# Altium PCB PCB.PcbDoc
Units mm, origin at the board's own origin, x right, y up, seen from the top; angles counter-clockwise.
Board outline 41 x 25.36 mm, 2 copper layers (TOP, BOTTOM), stack 1.586 mm thick; 42 components, 24 nets, 110 pads, 43 vias.
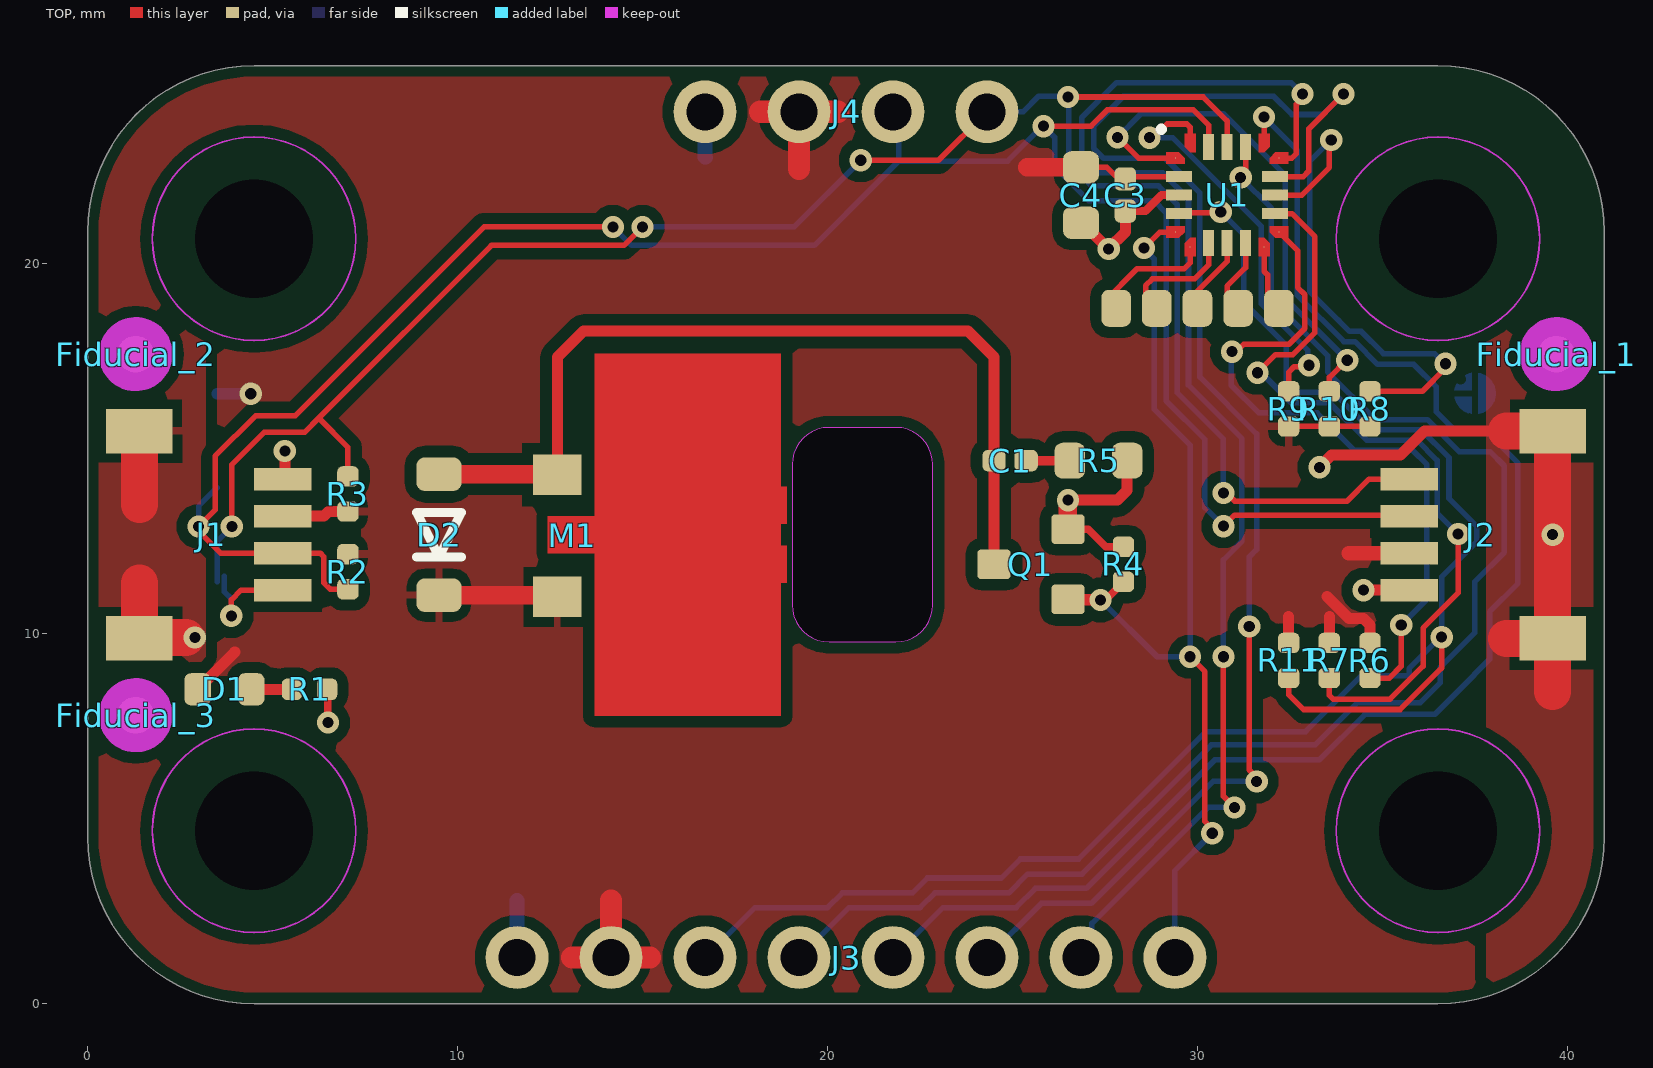
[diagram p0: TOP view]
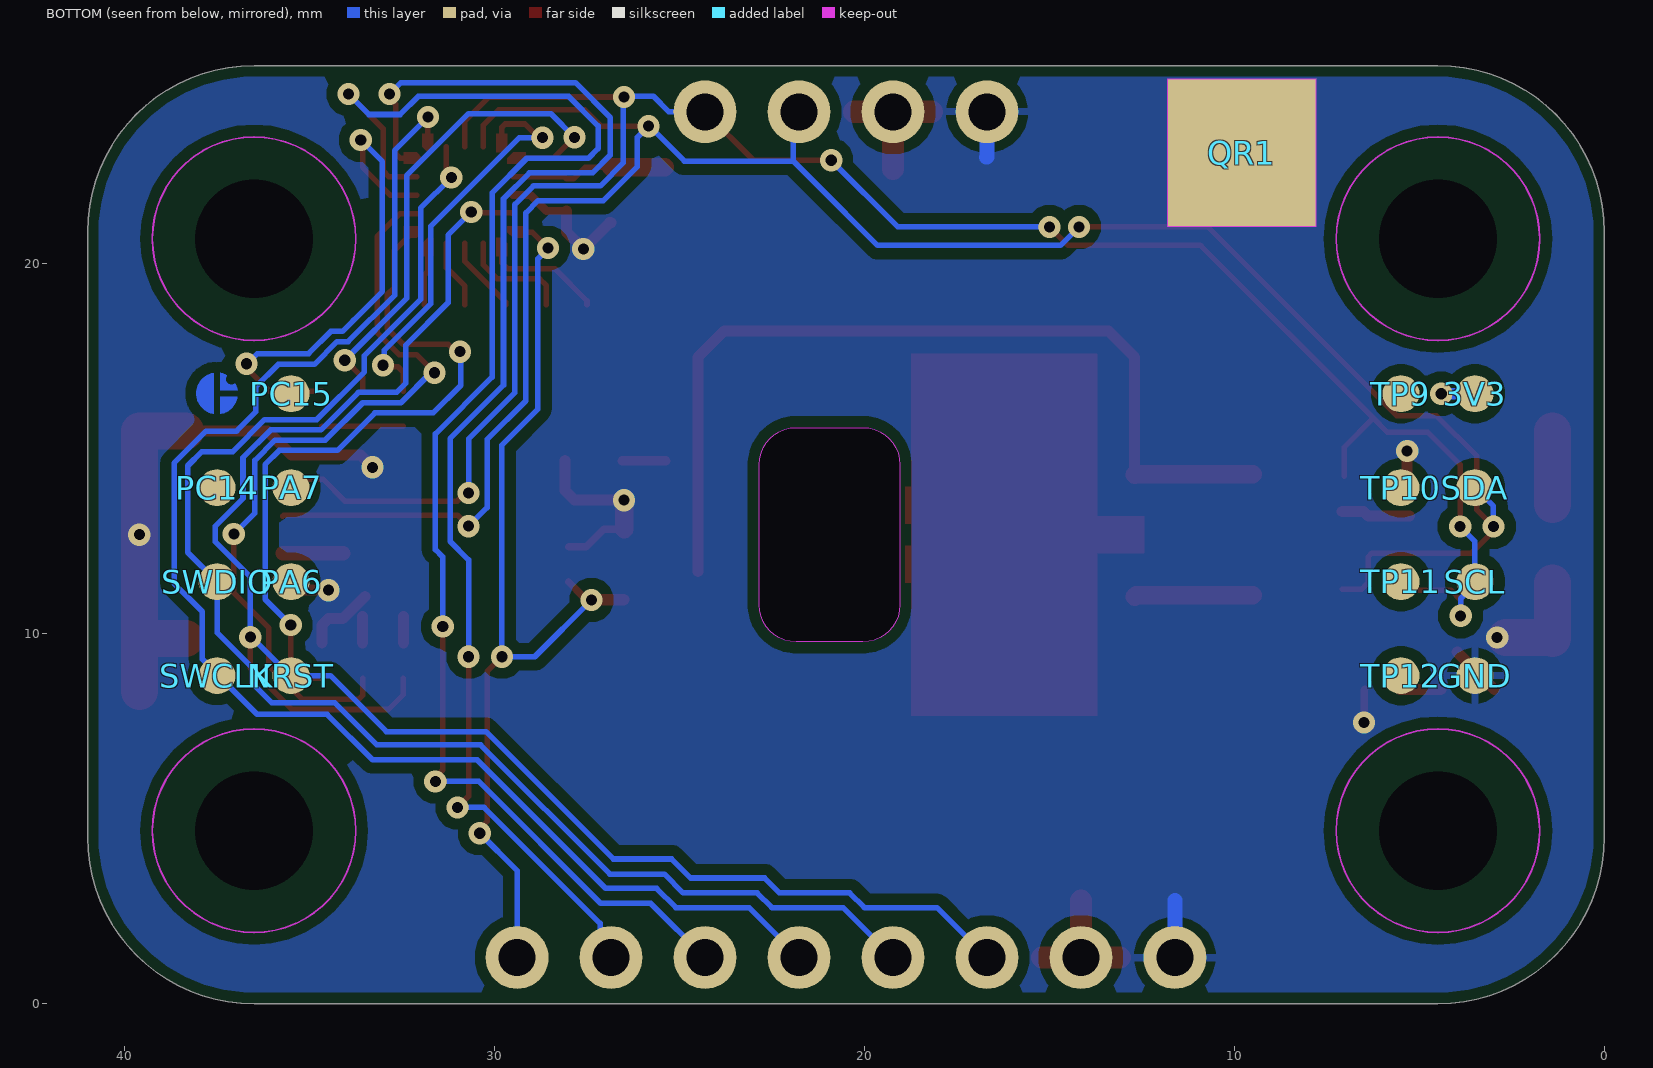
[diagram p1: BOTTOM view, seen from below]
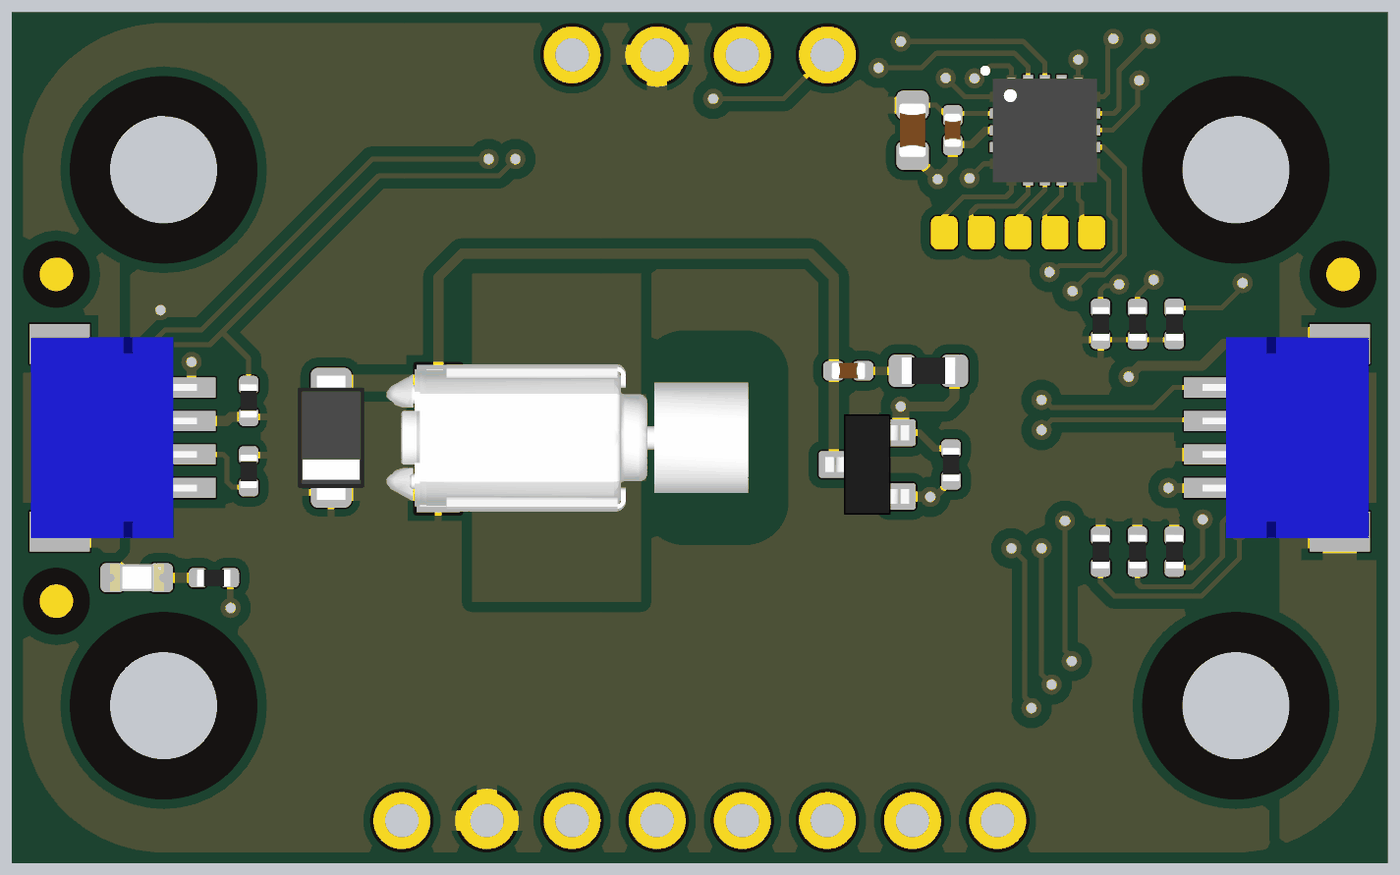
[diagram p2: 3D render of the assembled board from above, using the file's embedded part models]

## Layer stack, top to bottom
Top Solder: solder mask 0.01, Solder Resist, Dk 3.5
TOP: signal copper 0.018
Dielectric: core 1.55, FR-4, Dk 4.8
BOTTOM: signal copper 0.018
Bottom Solder: solder mask 0.01, Solder Resist, Dk 3.5

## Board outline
0,4.5 ccw(c4.5,4.5) 4.5,0 36.5,0 ccw(c36.5,4.5) 41,4.5 41,20.86 ccw(c36.5,20.86) 36.5,25.36 4.5,25.36 ccw(c4.5,20.86) 0,20.86
cut-out: 19.045,10.784 ccw(c20.045,10.784) 20.045,9.784 21.845,9.784 ccw(c21.845,10.784) 22.845,10.784 22.845,14.576 ccw(c21.845,14.576) 21.845,15.576 20.045,15.576 ccw(c20.045,14.576) 19.045,14.576

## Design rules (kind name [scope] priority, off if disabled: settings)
BoardOutlineClearance Motor [(ObjectKind = 'Pad') And (Layer = 'TOP') And (Name = 'M1-3')] p1: gap=0.1 ignorepadtopadclearanceinfootprint=FALSE
BoardOutlineClearance Mousebites [(ObjectKind = 'Pad') And (Name = 'Free-MOUSEBITE')] p2: gap=0 ignorepadtopadclearanceinfootprint=FALSE
BoardOutlineClearance Silks [(OnLayer('Top Overlay') OR OnLayer('Bottom Overlay'))] p3: gap=0 ignorepadtopadclearanceinfootprint=FALSE
BoardOutlineClearance [All] p4: gap=0.3 ignorepadtopadclearanceinfootprint=FALSE
Clearance MotorPad_clearance [(ObjectKind = 'Pad') And (Layer = 'TOP') And (Name = 'M1-3') vs (ObjectKind = 'Region') And (Layer = 'MultiLayer') And (Net = 'No Net')] p1: gap=0.05 ignorepadtopadclearanceinfootprint=FALSE
Clearance COPPER_0.3mm [All] p2: gap=0.127 ignorepadtopadclearanceinfootprint=FALSE except(0.3: Arc-Fill Arc-Poly Arc-Region Track-Fill Track-Poly Track-Region SMDPad-Fill SMDPad-Poly SMDPad-Region THPad-Fill THPad-Poly THPad-Region Via-Fill Via-Poly Via-Region Fill-Fill Fill-Poly Fill-Region Poly-Poly Poly-Region Region-Region)
Clearance "Generic clearance 0.15mm" [All] p3: gap=0.15 ignorepadtopadclearanceinfootprint=FALSE
ComponentClearance [All] p1: gap=0.2 collisioncheckmode=3 verticalgap=0 showdistances=TRUE
DiffPairsRouting USB [InDifferentialPairClass('USB')] p1: maxlimit=0.15 minlimit=0.15 mostfreqgap=0.15 toplayer_minwidth=0.15 toplayer_maxwidth=0.21 toplayer_prefwidth=0.2 bottomlayer_minwidth=0.15 bottomlayer_maxwidth=0.21 bottomlayer_prefwidth=0.2 impedanceprofiledriven=TRUE impedanceprofileid={E6B00C31-4C8E-439C-824F-D2B2CDC26F9C} impedanceprofilevalue=90.000000 maxuncoupledlength=12.7
Height [All] p1: minheight=0 maxheight=30 prefheight=12.7
HoleSize [All] p1: absolutevalues=TRUE maxlimit=30 minlimit=0.3 maxpercent=80.000 minpercent=20.000
HoleToHoleClearance [All] p1: gap=0.25 allowstackedmicrovias=FALSE
MinimumAnnularRing [All] p1: minimumring=0.15
PlaneConnect [All] p1: pad.planeconnectstyle=Relief pad.reliefexpansion=0.508 pad.reliefentries=4 pad.reliefconductorwidth=0.254 pad.reliefairgap=0.254 via.planeconnectstyle=Direct via.reliefexpansion=0.508 via.reliefentries=4 via.reliefconductorwidth=0.254 via.reliefairgap=0.254
PolygonConnect PolygonConnect_QR [(ObjectKind = 'Pad') And (Name = 'QR1-PAD')] p1: connectstyle=Direct reliefconductorwidth=0.254 reliefentries=4 polygonreliefangle="90 Angle" airgapwidth=0.254
PolygonConnect [All] p2: thpad.connectstyle=Relief thpad.reliefconductorwidth=0.2 thpad.reliefentries=4 thpad.polygonreliefangle="90 Angle" thpad.airgapwidth=0.254 smdpad.connectstyle=Relief smdpad.reliefconductorwidth=0.2 smdpad.reliefentries=4 smdpad.polygonreliefangle="90 Angle" smdpad.airgapwidth=0.254 via.connectstyle=Direct via.reliefconductorwidth=0.254 via.reliefentries=4 via.polygonreliefangle="90 Angle" via.airgapwidth=0.254
RoomDefinition K36 [False vs False] p1: confinementstyle=ConfineIn formatcopy=TRUE lockcomponents=FALSE outline 12.1,25.6 15.4,25.6 15.4,22.8 12.1,22.8
RoomDefinition TOP [InComponentClass('TOP')] p2: confinementstyle=ConfineIn formatcopy=TRUE lockcomponents=FALSE outline 42.1,5.4 49.2,5.4 49.2,22.3 42.1,22.3
RoutingVias StandardVias [All] p1: holewidth=0.3 width=0.6 viastyle="Through Hole" minholewidth=0.3 minwidth=0.6 maxholewidth=0.3 maxwidth=0.6
SMDToCorner [All] p1: distance=39370
SilkToSilkClearance [All] p1: silktosilkclearance=0.2
SilkToSolderMaskClearance [IsPad] p1: minsilkscreentomaskgap=0.15 clearancetoexposedcopper=TRUE
SolderMaskExpansion VIAtented [IsVia] p1: expansion=0.102 istentingtop=TRUE
SolderMaskExpansion [All] p2: expansion=0.05 istentingtop=FALSE
SupplyNets "Schematic Supply Nets_1" [InNet('GND')] p1: voltage=0.000
SupplyNets "Schematic Supply Nets" [InNet('+3V3')] p2: voltage=0.000
UnConnectedPin [All] p1:
UnRoutedNet [NOT WithinRoom('K36')] p1: checkbadconnections=TRUE
ViasUnderSMD [All] p1: allowed=FALSE
Width StandardTraces [All] p1: maxlimit=5 minlimit=0.15 preferedwidth=0.15 minimp=50.000000 maximp=50.000000 favimp=50.000000
21 further rules are at their usual default settings.

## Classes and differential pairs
component class U_MICROCONTROLLER: C3 C4 R2 R3 R6 R7 R8 R9 R10 R11 U1
component class TOP: 3V3 C1 D1 D2 Fiducial_1 Fiducial_2 Fiducial_3 GND J1 J2 J3 J4 M1 NRST PA6 PA7 PC14 PC15 Q1 QR1 R1 R4 R5 SCL SDA SWCLK SWDIO TP9 TP10 TP11 TP12

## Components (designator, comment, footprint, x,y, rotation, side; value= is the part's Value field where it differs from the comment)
3V3 "Test point 1.00mm" TP-1.00MM 3.5,16.49 r90 bottom
C1 "GRM155R71H102KA01D" CAP-0402 24.935,14.68 r180 top value=1nF
C3 "0402B104K160CT" CAP-0402 28.05,21.86 r270 top value=100nF
C4 "GRM188R61C475KAAJD" CAP-0603 26.85,21.86 r90 top value=4.7µF
D1 "HSMG-C190" LEDC1608X80N-AK 3.7,8.5 r180 top
D2 "PMEG6020AELRX" SOD123-1 9.5,12.68 r90 top
Fiducial_1 "Fiducial mark 1mm" "Fiducial mark 1mm-Footprint-1" 39.7,17.56 r270 top
Fiducial_2 "Fiducial mark 1mm" "Fiducial mark 1mm-Footprint-1" 1.3,17.56 r270 top
Fiducial_3 "Fiducial mark 1mm" "Fiducial mark 1mm-Footprint-1" 1.3,7.8 r270 top
GND "Test point 1.00mm" TP-1.00MM 3.5,8.87 r90 bottom
J1 "SM04B-SRSS-TB(LF)(SN)" SM04B-SRSS-TB(LF)(SN)-Footprint-1 3.337,12.68 r90 top locked
J2 "SM04B-SRSS-TB(LF)(SN)" SM04B-SRSS-TB(LF)(SN)-Footprint-1 37.663,12.68 r270 top locked
J3 "HEADER TH 2.54mm VERT. 1x008POS" "PIN HEADER 2.54mm VERT. 1x8POS" 20.5,1.25 r0 top
J4 "HEADER TH 2.54mm VERT. 1x004POS" "PIN HEADER 2.54mm VERT. 1x4POS-Footprint-1" 20.5,24.11 r0 top
M1 "VZ43FM1B8230001L" VZ43FM1B8230001L 16.5,12.68 r180 top
NRST "Test point 1.00mm" TP-1.00MM 35.5,8.87 r180 bottom
PA6 "Test point 1.00mm" TP-1.00MM 35.5,11.41 r180 bottom
PA7 "Test point 1.00mm" TP-1.00MM 35.5,13.95 r180 bottom
PC14 "Test point 1.00mm" TP-1.00MM 37.5,13.95 r180 bottom
PC15 "Test point 1.00mm" TP-1.00MM 35.5,16.49 r180 bottom
Q1 "2N7002KT1G" SOT23 25.5,11.88 r90 top
QR1 "QR CODE 4x4mm" "QR CODE 4x4mm" 9.8,23 r180 bottom
R1 "CRCW04021K00FKEDC" RES-0402 6,8.5 r180 top value=1k
R2 "RC0402FR-074K7L" RES-0402 7.039,11.68 r90 top value=4.7k
R3 "RC0402FR-074K7L" RES-0402 7.039,13.78 r270 top value=4.7k
R4 "RC0402FR-074K7L" RES-0402 28,11.88 r90 top value=4.7k
R5 "CRCW060322R0FKEAC" RES-0603 27.325,14.68 r0 top value=22
R6 "RC0402FR-074K7L" RES-0402 34.663,9.28 r270 top value=4.7k
R7 "RC0402FR-074K7L" RES-0402 33.563,9.28 r270 top value=4.7k
R8 "RC0402FR-074K7L" RES-0402 34.663,16.08 r90 top value=4.7k
R9 "RC0402FR-074K7L" RES-0402 32.463,16.08 r90 top value=4.7k
R10 "RC0402FR-074K7L" RES-0402 33.563,16.08 r90 top value=4.7k
R11 "RC0402FR-074K7L" RES-0402 32.463,9.28 r270 top value=4.7k
SCL "Test point 1.00mm" TP-1.00MM 3.5,11.41 r90 bottom
SDA "Test point 1.00mm" TP-1.00MM 3.5,13.95 r90 bottom
SWCLK "Test point 1.00mm" TP-1.00MM 37.5,8.87 r180 bottom
SWDIO "Test point 1.00mm" TP-1.00MM 37.5,11.41 r180 bottom
TP9 "Test point 1.00mm" TP-1.00MM 5.5,16.49 r0 bottom
TP10 "Test point 1.00mm" TP-1.00MM 5.5,13.95 r0 bottom
TP11 "Test point 1.00mm" TP-1.00MM 5.5,11.41 r0 bottom
TP12 "Test point 1.00mm" TP-1.00MM 5.5,8.87 r0 bottom
U1 "STM32C011F6U6TR" UFQFPN20 30.8,21.86 r0 top

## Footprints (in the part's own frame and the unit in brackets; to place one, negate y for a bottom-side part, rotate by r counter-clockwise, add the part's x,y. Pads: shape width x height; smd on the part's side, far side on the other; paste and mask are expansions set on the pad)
CAP-0402 [mm] "Chip Capacitor, 2-Leads, Body  0402 (in) 1005 (mm), IPC Medium Density"
  rrect52% 0.63x0.58 smd mask+0.05: 1(-0.435,0) 2(0.435,0)
  body extent -0.5,-0.25 0.5,0.25, height 0.5
CAP-0603 [mm] "Chip Capacitor, Body 0603 imperial,1.6x0.8mm, IPC High Density"
  rrect51% 0.87x0.97 smd mask+0.05: 1(-0.75,0) 2(0.75,0)
  body extent -0.8,-0.4 0.8,0.4, height 0.8
"Fiducial mark 1mm-Footprint-1" [mm]
  round 1 smd paste-10 mask+0.5: 1(0,0)
  TOP keep-out circle w1: c0,0 r0.5
LEDC1608X80N-AK [mm]
  rrect50% 0.72x0.87 smd: A(0.725,0) C(-0.725,0)
  body extent -0.8,-0.4 0.8,0.4, height 0.79
"PIN HEADER 2.54mm VERT. 1x4POS-Footprint-1" [mm]
  round 1.7 hole 1 mask+0.1: 1(-3.81,0) 2(-1.27,0) 3(1.27,0) 4(3.81,0)
"PIN HEADER 2.54mm VERT. 1x8POS" [mm]
  round 1.7 hole 1 mask+0.1: 1(-8.89,0) 2(-6.35,0) 3(-3.81,0) 4(-1.27,0) 5(1.27,0) 6(3.81,0) 7(6.35,0) 8(8.89,0)
"QR CODE 4x4mm" [mm]
  rect 4x4 smd paste-2539.97 mask+0.1: PAD(0,0)
  TOP keep-out region: -2,2 2,2 2,-2 -2,-2
RES-0402 [mm] "Chip Resistor, 2-Leads, Body  0402 (in) 1005 (mm), IPC Medium Density"
  rrect51% 0.55x0.58 smd mask+0.05: 1(-0.475,0) 2(0.475,0)
  body extent -0.5,-0.25 0.5,0.25, height 0.34
RES-0603 [mm] "Chip Resistor - Body 0603 imperial,1.6x0.8mm, IPC High Density"
  rrect51% 0.82x0.97 smd mask+0.05: 1(-0.775,0) 2(0.775,0)
  body extent -0.8,-0.4 0.8,0.4, height 0.43
SM04B-SRSS-TB(LF)(SN)-Footprint-1 [mm]
  rect 0.6x1.55 smd mask+0.05: 1(1.5,-1.937) 2(0.5,-1.937) 3(-0.5,-1.937) 4(-1.5,-1.937)
  rect 1.2x1.8 smd mask+0.05: FIX(-2.8,1.938) FIX(2.8,1.938)
  body extent -3,-2.16 3,2.8, height 2.98
SOD123-1 [mm]
  rrect50% 0.91x1.22 smd: A(1.635,0) C(-1.635,0)
  silkscreen extent -0.6,-0.6 0.6,0.6, body extent -1.85,-1 1.85,1, height 1.2
SOT23 [mm]
  rrect25% 0.8x0.9 smd: 1(-0.95,-1) 2(0.95,-1) 3(0,1)
  body extent -1.5,-1.25 1.5,1.25, height 1.05
TP-1.00MM [mm]
  rrect100% 1x1 smd paste-2.54: X(0,0)
UFQFPN20 [mm] "QFN, 20-Leads, Body 3.00x3.00mm, Pitch 0.50mm, IPC Medium Density"
  round 0.025 smd mask+0.05: 1(-1.4,1) 5(-1.4,-1) 6(-1,-1.4) 10(1,-1.4) 11(1.4,-1) 15(1.4,1) 16(1,1.4) 20(-1,1.4)
  rect 0.7x0.3 smd mask+0.05: 2(-1.3,0.5) 3(-1.3,0) 4(-1.3,-0.5) 12(1.3,-0.5) 13(1.3,0) 14(1.3,0.5)
  rect 0.3x0.7 smd mask+0.05: 7(-0.5,-1.3) 8(0,-1.3) 9(0.5,-1.3) 17(0.5,1.3) 18(0,1.3) 19(-0.5,1.3)
  TOP region: 1.65,-0.85 1.65,-1.15 1.3,-1.15 1.15,-1 1.15,-0.85
  TOP region: -1.15,1.3 -1,1.15 -0.85,1.15 -0.85,1.65 -1.15,1.65
  TOP region: -1.15,1 -1.15,0.85 -1.65,0.85 -1.65,1.15 -1.3,1.15
  TOP region: 1,1.15 0.85,1.15 0.85,1.65 1.15,1.65 1.15,1.3
  TOP region: 1.65,1.15 1.65,0.85 1.15,0.85 1.15,1 1.3,1.15
  TOP region: 1.15,-1.65 0.85,-1.65 0.85,-1.15 1,-1.15 1.15,-1.3
  TOP region: -0.85,-1.65 -1.15,-1.65 -1.15,-1.3 -1,-1.15 -0.85,-1.15
  TOP region: -1.3,-1.15 -1.15,-1 -1.15,-0.85 -1.65,-0.85 -1.65,-1.15
  silkscreen extent -1.8,1.75 -1.75,1.8, body extent -1.55,-1.55 1.55,1.55, height 0.6
VZ43FM1B8230001L [mm]
  rect 1.3x1.1 smd mask+0.1: 1(3.805,-1.622) 2(3.805,1.678)
  round 0.025 smd paste-2539.97 mask+0.1: 3(3,0)
  TOP region: 4.055,-0.5 4.055,0.5 2.555,0.5 2.555,1.7 -1.745,1.7 -1.745,1.3 -2.395,1.3 -2.395,0.3 -1.745,0.3 -1.745,-0.3 -2.395,-0.3 -2.395,-1.3 -1.745,-1.3 -1.745,-1.7 2.555,-1.7 2.555,-0.5
  body extent -5.45,-2.2 5.35,2.2, height 3.6

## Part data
3V3 GND NRST PA6 PA7 PC14 PC15 SCL SDA SWCLK SWDIO TP9 TP10 TP11 TP12: library part UT0013-A.6, Manufacturer="This is not a component"
C1: library part C0007-A.15, "CAP CHIP 0402 1nF 10% 50V X7R", Case Code (Imperial)=0402, Dielectric=X7R, Manufacturer=KEMET, Tolerance=10%, Voltage=50V
C3: library part C0012-A.15, "CAP CHIP 0402 100nF 10% 16V X7R", Case Code (Imperial)=0402, Dielectric=X7R, Manufacturer=Walsin, Tolerance=10%, Voltage=16V
C4: library part C0054-A.16, "CAP CHIP 0603 4.7uF 10% 16V X5R", Case Code (Imperial)=0603, Dielectric=X5R, Manufacturer=Murata, Manufacturer 3="Samsung Electro-Mechanics", Part number 2=GRM188R61C475KE11D, Part number 3=CL10A475KO8NNNC, Tolerance=10%, Voltage=16V
D1: library part L0009-A.5, "LED SMD 0603 GREEN/568 15mcd 120^", Manufacturer=Broadcom
D2: library part D0026-A.6, "DIODE SCHOTTKY SMD 2A 60V SOD123FL", Forward Current=2A, Forward Voltage=0.6V, Manucturer Part Number 2=SS26L, Manufacturer=Nexperia
Fiducial_1 Fiducial_2 Fiducial_3: library part UT0023-A.7, "Fiducial mark 1mm clearance 2mm"
J1 J2: library part J0005-A.2, "CONN JST 4POS SIDE 1MM TIN QWIIC", Manufacturer=JST
J3: library part J0171-A.4
J4: library part J0162-A.6
M1: library part S0061-A.3, "MOTOR vibrator, 2.3V to 3.2V, max 75mA, 14000 RPM, DO NOT WASH, heigth 3.4mm, overall length 11mm", Manufacturer="Vybronics Inc"
Q1: library part T0004-A.10, "MOSFET N-CH 60V 300mA ESD prot. SOT23", Manufacturer="On Semiconductor", Manufacturer 2=Hottech, Manufacturer Part Number 2=2N7002K
QR1: library part QR-0001-A.5, "QR CODE 4x4mm on layer 34 (This is not a component)", Manufacturer="This is not a component"
R1: library part R0007-A.24, "RES CHIP 0402 1k 1% 1/16W", Case Code (Imperial)=0402, Manufacturer=Vishay, Power=62.5mW, Temperature Coefficient=100ppm, Tolerance=1%
R2 R3 R4 R6 R7 R8 R9 R10 R11: library part R0013-A.24, "RES CHIP 0402 4k7 1% 1/16W", Case Code (Imperial)=0402, Manufacturer=YAGEO, Power=62.5mW, Temperature Coefficient=200ppm, Tolerance=1%
R5: library part R0121-A.22, "RES CHIP 0603 22R 1% 1/10W", Case Code (Imperial)=0603, Manufacturer=Vishay, Power=100mW, Temperature Coefficient=100ppm, Tolerance=1%
U1: library part U0390-A.1, "IC Cortex M0, 32b MCU, 32KB Flash, 6KB RAM, VDD 2-3.6V, -40°C to 85°C, QFN20 3x3mm", Manufacturer="ST Microelectronics"

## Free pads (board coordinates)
  rrect50% 0.8x1 smd paste-2539.97: 3V8(28.9,18.8) 3V9(27.8,18.8) 3V9(30,18.8) 3V10(31.1,18.8) 3V10(32.2,18.8)
  round 3 hole 3.2 unplated paste-2539.97 mask+1.3: MH(4.5,4.68) MH(4.5,20.68) MH(36.5,4.68) MH(36.5,20.68)

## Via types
v1: diameter 0.6, hole 0.3, TOP to BOTTOM, tented both sides, 43 vias

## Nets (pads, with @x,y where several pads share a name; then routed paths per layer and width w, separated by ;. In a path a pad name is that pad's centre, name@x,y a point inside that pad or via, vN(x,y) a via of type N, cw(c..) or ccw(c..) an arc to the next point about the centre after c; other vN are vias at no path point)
+3V3: 3V3.X C3.1 C4.2 D1.A D2.C J1.2 J2.2 J3.2 J4.2 M1.2 R2.2 R3.2 R6.1 R7.1 R8.1 R9.1 R10.1 R11.1 U1.2 | length 26.2
  TOP w0.15: C4.2 27.55,22.61 27.865,22.295 C3.1 28.115,22.36 U1.2 ; R9.1 R10.1 R8.1
  TOP w0.3: D1.A 3.98,9.505 ; J1.2 6.389,13.18 6.514,13.305 R3.2@7.089,13.305 ; R11.1 32.463,10.463 ; 33.5,11.01 34.1,10.41 34.487,10.41 34.663,10.234 R6.1 ; R7.1 33.563,10.463
  TOP w0.4: 34.088,12.18 J2.2
  TOP w0.5: D2.C 12.652,11.045 M1.2 ; 25.4,22.61 C4.2
  TOP w0.6: 13.1,1.25 J3.2 ; 14.15,2.79 J3.2 ; 15.2,1.25 J3.2 ; 18.18,24.11 J4.2 ; 19.23,22.57 J4.2 ; 20.28,24.11 J4.2
  BOTTOM w0.3: 3V3.X v1(4.41,16.49)
GND: C3.2 C4.1 GND.X J1.1 J1.FIX J2.1 J2.FIX J3.1 J4.1 Q1.2 QR1.PAD R1.1 R4.2 R5.2 U1.3 | length 37.1
  TOP w0.2: R1.1 6.488,8.488 6.488,7.612 v1(6.5,7.6) ; Q1.2 27.05,12.83 27.525,12.355 R4.2
  TOP w0.22: C3.2 28.592,21.425 29.027,21.86 U1.3
  TOP w0.3: J1.1 5.332,14.238 v1(5.332,14.942) ; v1(26.497,13.612) 27.832,13.612 28.1,13.88 R5.2 ; C4.1 26.895,21.11 v1@27.6,20.405 ; v1(27.6,20.4) v1@27.6,20.405 ; C3.2 28.05,20.866 27.6,20.416 v1@27.6,20.405 ; v1(33.3,14.5) 33.628,14.828 35.486,14.828 36.138,15.48 J2.FIX@39.601,15.48 ; v1(34.488,11.18) J2.1
  TOP w0.5: J1.FIX@1.399,9.88 1.419,9.9 v1(2.9,9.9) ; v1(26.497,13.612) 26.498,13.611 26.498,12.832 Q1.2
  TOP w1: J1.FIX@1.399,9.88 1.399,11.379 ; 1.399,13.499 J1.FIX@1.399,15.48 ; J1.FIX@1.419,9.9 v1@2.667,9.9 ; 38.353,9.88 J2.FIX@39.601,9.88 ; 38.353,15.48 39.601,15.48 J2.FIX@39.601,9.88 ; 39.601,8.443 J2.FIX@39.601,9.88
  BOTTOM w0.4: J3.1 11.61,2.79 ; J4.1 16.69,22.89 16.7,22.88
  other v1: 39.601,12.68
NetC1_1: C1.1 R5.1 | length 1.2
  TOP w0.25: C1.1 R5.1
NetC1_2: C1.2 D2.A M1.1 Q1.3 | length 24.6
  TOP w0.3: M1.1 12.7,14.307 12.7,17.48 13.4,18.18 23.8,18.18 24.5,17.48 C1.2 Q1.3@24.5,11.68
  TOP w0.5: D2.A 12.682,14.315 M1.1
NetD1_C: D1.C R1.2 | length 1.1
  TOP w0.3: D1.C R1.2
NetU1_6: pad.3V9@27.8,18.8 U1.6 | length 3.3
  TOP w0.15: pad.3V9@27.5,18.9 27.5,19 28.373,19.873 29.644,19.873 29.8,20.028 U1.6
NetU1_7: pad.3V8 U1.7 | length 3
  TOP w0.15: pad.3V8@28.6,18.9 28.6,19.415 28.781,19.596 29.925,19.596 30.3,19.971 U1.7
NetU1_8: pad.3V9@30,18.8 U1.8 | length 2.1
  TOP w0.15: pad.3V9@29.7,18.9 29.7,18.968 30.8,20.068 U1.8
NetU1_9: pad.3V10@31.1,18.8 U1.9 | length 1.9
  TOP w0.15: pad.3V10@30.8,18.9 30.8,19.4 31.3,19.9 U1.9
NetU1_10: pad.3V10@32.2,18.8 U1.10 | length 1.6
  TOP w0.15: U1.10 31.8,19.8 31.9,19.7 pad.3V10@31.9,18.9
PA0_1: J3.8 Q1.1 R4.1 U1.5 | length 26.2
  TOP w0.15: v1(28.552,20.428) 28.984,20.86 U1.5 ; v1(29.8,9.38) 30.2,8.98 30.2,4.932 30.4,4.732 v1(30.4,4.61)
  TOP w0.2: v1(27.378,10.914) 27.455,10.991 27.586,10.991 R4.1
  TOP w0.3: Q1.1 26.508,10.922 27.37,10.922 v1(27.378,10.914)
  BOTTOM w0.15: v1(27.378,10.914) 28.912,9.38 v1(29.8,9.38) 29.8,15.1 28.828,16.072 28.828,20.138 28.552,20.413 v1(28.552,20.428) ; J3.8 29.39,3.6 v1(30.4,4.61)
PA6_2: R6.2 U1.11 | length 18.9
  TOP w0.15: v1(30.937,17.626) 31.053,17.626 31.249,17.823 32.466,17.823 32.899,18.255 32.899,19.17 32.705,19.364 32.705,20.355 U1.11 ; R6.2 35.184,8.805 35.508,9.128 v1(35.508,10.241)
  BOTTOM w0.15: v1(30.937,17.626) 30.913,17.602 30.913,16.717 31.66,15.97 33.233,15.97 34.246,14.957 35.818,14.957 36.202,14.573 36.202,10.935 v1(35.508,10.241)
PA7_2: R7.2 U1.12 | length 21.4
  TOP w0.15: v1(31.624,17.056) 31.68,17.113 32.113,17.546 32.581,17.546 33.176,18.141 33.176,20.734 32.55,21.36 U1.12 ; R7.2 33.563,8.337 33.665,8.234 35.203,8.234 36.098,9.129 36.098,10.158 37.054,11.114 37.054,12.689 v1(37.046,12.697)
  BOTTOM w0.15: v1(31.624,17.056) 31.723,17.056 32.533,16.247 33.562,16.247 34.575,15.234 35.933,15.234 36.479,14.688 36.479,13.264 v1(37.046,12.697)
PA8_2: R8.2 U1.13 | length 13.8
  TOP w0.15: U1.13 32.822,21.86 33.567,22.605 33.567,23.3 v1(33.615,23.347) ; R8.2 36.075,16.555 36.7,17.18 v1(36.7,17.3)
  BOTTOM w0.15: v1(33.615,23.347) 33.029,22.762 33.029,19.258 33.816,18.471 34.114,18.173 34.427,18.173 35.027,17.573 36.408,17.573 36.681,17.3 v1(36.7,17.3)
PA9_USART1_TX_1: J3.6 U1.14 | length 40.9
  TOP w0.15: v1(31.4,10.2) 31.4,6.323 31.6,6.123 v1(31.6,6.01) ; U1.14 32.86,22.36 33.008,22.508 33.008,23.648 v1(33.95,24.59)
  BOTTOM w0.15: J3.6 25.778,2.718 27.133,2.718 30.425,6.01 v1(31.6,6.01) ; v1(31.4,10.2) 31.4,12.078 31.6,12.278 31.6,15.404 30.067,16.938 30.067,21.917 29.13,22.854 27.463,22.854 27.199,23.118 27.199,23.73 27.998,24.53 32.058,24.53 32.551,24.037 33.397,24.037 v1(33.95,24.59)
PA10_USART1_RX_1: J3.7 U1.15 | length 36.7
  TOP w0.15: v1(30.7,9.38) 30.7,5.61 v1(31,5.31) ; U1.15 32.554,22.86 32.671,22.977 32.671,24.312 32.841,24.482 v1(32.841,24.591)
  BOTTOM w0.15: J3.7 27.147,1.547 27.147,2.172 30.285,5.31 v1(31,5.31) ; v1(30.7,9.38) 30.7,12 31.202,12.502 31.202,15.276 29.757,16.72 29.757,21.759 29.056,22.46 27.35,22.46 26.871,22.939 26.871,23.956 27.816,24.9 32.531,24.9 v1(32.841,24.591)
PA13_SWDIO_1: J3.5 SWCLK.X U1.16 | length 39.3
  TOP w0.15: v1@31.744,24.019 v1(31.795,23.968) 31.8,23.963 U1.16
  BOTTOM w0.15: J3.5 23.12,2.6 25.1,2.6 25.618,3.118 26.993,3.118 30.471,6.596 33.296,6.596 34.523,7.823 36.413,7.823 37.48,8.89 37.48,8.899 37.9,9.319 37.9,10.6 38.662,11.362 38.662,14.617 37.798,15.481 36.974,15.481 36.456,16 36.456,16.672 35.846,17.282 34.869,17.282 34.255,17.896 33.955,17.896 32.702,19.149 32.702,23.061 v1(31.795,23.968)
PA14_SWCLK_BOOT0_1: J3.4 SWDIO.X U1.17 | length 39.9
  TOP w0.15: v1(31.167,22.336) 31.167,22.429 31.3,22.562 U1.17
  BOTTOM w0.15: J3.4 20.58,2.6 22.5,2.6 22.9,3 24.9,3 25.407,3.507 26.881,3.507 30.375,7 33.181,7 34.324,8.143 36.027,8.143 36.557,8.673 36.557,9.089 37.5,10.032 SWDIO.X 38.291,12.201 38.291,14.543 37.907,14.927 37.073,14.927 36.212,15.788 34.804,15.788 33.516,17.077 33.516,17.52 31.998,19.038 31.998,21.506 v1(31.167,22.336)
PC14_2: R9.2 U1.20 | length 11.1
  TOP w0.15: v1(28.7,23.41) 28.808,23.41 29.178,23.781 29.712,23.781 29.8,23.693 U1.20 ; R9.2 32.463,17.068 32.614,17.219 32.973,17.219 v1(33.014,17.259)
  BOTTOM w0.15: v1(28.7,23.41) 29.33,23.41 31.721,21.02 31.721,18.924 32.985,17.659 v1@32.985,17.288
PC15_2: R10.2 U1.1 | length 14
  TOP w0.15: v1@27.85,23.42 28.41,22.86 U1.1 ; R10.2 33.563,16.93 34.027,17.394 v1(34.047,17.394)
  BOTTOM w0.15: v1(27.84,23.42) 28.48,24.06 30.698,24.06 32.375,22.383 32.375,19.066 v1(34.047,17.394)
PF2_N\R\S\T\_1: J3.3 NRST.X R11.2 U1.4 | length 47
  TOP w0.15: U1.4 29.52,21.38 30.61,21.38 v1(30.63,21.4) ; R11.2 32.463,8.359 32.866,7.955 35.479,7.955 36.6,9.076 v1(36.6,9.91)
  BOTTOM w0.15: J3.3 18.04,2.6 20,2.6 20.4,3 22.3,3 22.7,3.4 24.7,3.4 25.214,3.914 26.788,3.914 30.233,7.359 32.923,7.359 34.434,8.87 NRST.X 35.722,8.87 35.722,9.062 36.57,9.91 v1(36.6,9.91) 36.6,11.54 37.553,12.493 37.553,12.905 36.798,13.659 36.798,14.761 36.048,15.511 34.69,15.511 33.677,16.524 32.647,16.524 32.396,16.776 32.396,17.805 31.252,18.948 31.252,20.778 v1(30.63,21.4)
Rotor_1: M1.3
SCL_1: J1.4 J2.4 J4.4 R3.1 SCL.X U1.18 | length 59.2
  TOP w0.15: v1(3.886,10.486) 3.886,10.916 4.15,11.18 J1.4 ; v1(3.9,12.9) 3.9,14.573 4.78,15.453 5.873,15.453 6.25,15.83 ; R3.1 7.039,15.041 6.25,15.83 ; v1(15,21) 14.498,20.498 10.918,20.498 6.25,15.83 ; v1(20.9,22.8) 23,22.8 J4.4 ; v1(26.5,24.51) 30.151,24.51 30.8,23.861 U1.18 ; v1(30.7,13.81) 30.786,13.81 31.013,13.583 34.041,13.583 34.638,14.18 J2.4
  BOTTOM w0.15: SCL.X 3.5,12.5 v1(3.9,12.9) ; SCL.X@3.694,11.557 3.694,11.14 3.886,10.948 v1(3.886,10.486) ; v1(15,21) 19.1,21 v1(20.9,22.8) ; J4.4 25.288,24.11 25.71,24.532 26.478,24.532 v1(26.5,24.51) 26.516,24.494 26.516,22.735 27.141,22.11 28.947,22.11 29.452,21.605 29.452,16.518 30.7,15.27 v1(30.7,13.81)
SDA_1: J1.3 J2.3 J4.3 R2.1 SDA.X U1.19 | length 60.9
  TOP w0.15: R2.1@7.089,11.205 6.564,11.205 6.49,11.28 6.389,11.38 6.389,12.08 6.289,12.18 J1.3 3.598,12.18 3.186,12.592 3,12.778 v1(3,12.9) 3.448,13.348 3.448,14.801 4.547,15.9 5.62,15.9 10.72,21 v1(14.2,21) ; v1(25.838,23.722) 27.122,23.722 27.56,24.16 29.888,24.16 30.3,23.748 U1.19 ; v1(30.7,12.91) 31,13.21 35.696,13.21 J2.3
  BOTTOM w0.15: v1(3,12.9) 3,13.45 SDA.X ; v1(14.2,21) 14.702,20.498 19.648,20.498 21.355,22.205 21.926,22.776 ; J4.3 21.926,23.954 21.926,22.776 ; v1(30.7,12.91) 30.198,13.412 30.198,15.257 29.155,16.3 29.155,21.375 28.819,21.71 27.058,21.71 26.138,22.629 26.138,23.422 v1(25.838,23.722) 25.814,23.722 24.869,22.776 21.926,22.776
pads on no net: Fiducial_1.1 Fiducial_2.1 Fiducial_3.1 PA6.X PA7.X PC14.X PC15.X TP9.X TP10.X TP11.X TP12.X

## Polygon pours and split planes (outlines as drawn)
+3V3 on TOP "NONET_L04_P-001" (solid, remove dead copper, pour order 8): 0,4.5 ccw(c4.5,4.5) 4.5,0 36.5,0 ccw(c36.5,4.5) 41,4.5 41,20.86 ccw(c36.5,20.86) 36.5,25.36 4.5,25.36 ccw(c4.5,20.86) 0,20.86
GND on TOP "NONET_L04_P-001" (solid, remove dead copper, pour order 5): 0,25.36 0,0 3.2,0 3.2,25.36
GND on TOP "NONET_L04_P-001" (solid, remove dead copper, pour order 6): 41,25.36 41,0 37.8,0 37.8,25.36
GND on BOTTOM "NONET_L04_P-001" (solid, remove dead copper, pour order 9): 0,4.5 ccw(c4.5,4.5) 4.5,0 36.5,0 ccw(c36.5,4.5) 41,4.5 41,20.86 ccw(c36.5,20.86) 36.5,25.36 4.5,25.36 ccw(c4.5,20.86) 0,20.86

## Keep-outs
Keep-Out Layer:
  circle w0.05: c36.5,4.68 r2.75
  circle w0.05: c36.5,20.68 r2.75
  circle w0.05: c4.5,4.68 r2.75
  circle w0.05: c4.5,20.68 r2.75

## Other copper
TOP:
  rectangle net Rotor_1: 13.7,7.78 18.745,17.58
BOTTOM:
  region: 37.415,16.266 37.415,15.955 37.408,15.955 37.408,15.949 37.382,15.949 37.382,15.955 37.375,15.955 37.375,15.962 37.335,15.962 37.335,15.969 37.309,15.969 37.309,15.975 37.302,15.975 37.302,15.982 37.289,15.982 37.289,15.989 37.282,15.989 37.282,15.995 37.269,15.995 37.269,15.989 37.256,15.989 37.256,16.002 37.236,16.002 37.236,16.008 37.229,16.008 37.229,16.015 37.223,16.015 37.223,16.022 37.203,16.022 37.203,16.028 37.196,16.028 37.196,16.035 37.183,16.035 37.183,16.041 37.177,16.041 37.177,16.048 37.17,16.048 37.17,16.055 37.157,16.055 37.157,16.068 37.137,16.068 37.137,16.075 37.13,16.075 37.13,16.081 37.124,16.081 37.124,16.088 37.117,16.088 37.117,16.094 37.11,16.094 37.11,16.101 37.104,16.101 37.104,16.108 37.097,16.108 37.097,16.114 37.091,16.114 37.091,16.121 37.084,16.121 37.084,16.127 37.077,16.127 37.077,16.134 37.071,16.134 37.071,16.154 37.064,16.154 37.064,16.161 37.057,16.161 37.057,16.167 37.051,16.167 37.051,16.174 37.044,16.174 37.044,16.187 37.038,16.187 37.038,16.194 37.031,16.194 37.031,16.2 37.024,16.2 37.024,16.207 37.018,16.207 37.018,16.227 37.011,16.227 37.011,16.247 36.998,16.247 36.998,16.266 36.991,16.266 36.991,16.286 36.978,16.286 36.978,16.319 36.971,16.319 36.971,16.326 36.965,16.326 36.965,16.339 36.971,16.339 36.971,16.346 36.965,16.346 36.965,16.352 36.958,16.352 36.958,16.405 37.408,16.405 37.408,16.399 37.415,16.399 37.415,16.273
  region: 36.978,16.584 36.945,16.584 36.945,16.591 36.952,16.591 36.952,16.597 36.958,16.597 36.958,16.65 36.965,16.65 36.965,16.657 36.971,16.657 36.971,16.663 36.965,16.663 36.965,16.677 36.971,16.677 36.971,16.683 36.978,16.683 36.978,16.71 36.985,16.71 36.985,16.716 36.991,16.716 36.991,16.729 36.998,16.729 36.998,16.749 37.005,16.749 37.005,16.756 37.011,16.756 37.011,16.763 37.024,16.763 37.024,16.756 37.038,16.756 37.038,16.749 37.044,16.749 37.044,16.743 37.064,16.743 37.064,16.736 37.071,16.736 37.071,16.729 37.157,16.729 37.157,16.743 37.19,16.743 37.19,16.749 37.196,16.749 37.196,16.756 37.203,16.756 37.203,16.763 37.21,16.763 37.21,16.769 37.216,16.769 37.216,16.776 37.223,16.776 37.223,16.782 37.229,16.782 37.229,16.789 37.236,16.789 37.236,16.796 37.243,16.796 37.243,16.802 37.249,16.802 37.249,16.809 37.256,16.809 37.256,16.829 37.263,16.829 37.263,16.941 37.256,16.941 37.256,16.961 37.249,16.961 37.249,16.968 37.243,16.968 37.243,16.974 37.236,16.974 37.236,16.987 37.243,16.987 37.243,16.994 37.263,16.994 37.263,17.007 37.282,17.007 37.282,17.014 37.289,17.014 37.289,17.02 37.315,17.02 37.315,17.027 37.349,17.027 37.349,17.04 37.388,17.04 37.388,17.047 37.395,17.047 37.395,17.054 37.408,17.054 37.408,17.047 37.415,17.047 37.415,16.591 37.408,16.591 37.408,16.584 36.985,16.584
  region: 197 vertices and 0 holes, not listed, extent 37.593,15.949 38.056,17.047

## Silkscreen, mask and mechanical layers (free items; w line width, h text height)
Route Tool Path:
  lines w2: -1,8.498 -1,16.86 ; 42,4.5 cw(c36.5,4.5) 36.5,-1 ; 42,8.498 42,16.86 ; -1,4.498 cw(c0,4.5) -1,4.5 ccw(c4.5,4.5) -1,4.498 ; -1,4.498 ccw(c4.5,4.5) 4.498,-1 ; -1,20.86 cw(c4.5,20.86) 4.5,26.36 ; -1,20.86 -1,20.86 ; 4.498,-1 ccw(c4.5,0) 4.5,-1 ; 4.498,-1 ccw(c4.5,4.5) 4.5,-1 ; 4.5,-1 36.5,-1 ; 4.5,26.36 4.5,26.36 ; 4.5,26.36 36.5,26.36 ; 36.5,-1 36.5,-1 ; 36.5,26.36 cw(c36.5,25.36) 36.502,26.36 ; 36.5,26.36 cw(c36.5,20.86) 36.502,26.36 ; 36.502,26.36 cw(c36.5,20.86) 42,20.863 ; 42,20.863 cw(c36.5,20.86) 42,20.86 ccw(c41,20.86) 42,20.863
Board:
  lines w0.05: 0,4.5 ccw(c4.5,4.5) 4.5,0 36.5,0 ccw(c36.5,4.5) 41,4.5 41,20.86 ccw(c36.5,20.86) 36.5,25.36 4.5,25.36 ccw(c4.5,20.86) 0,20.86 0,4.5
  lines w0.1: 19.045,10.784 ccw(c20.045,10.784) 20.045,9.784 21.845,9.784 ccw(c21.845,10.784) 22.845,10.784 22.845,14.576 ccw(c21.845,14.576) 21.845,15.576 20.045,15.576 ccw(c20.045,14.576) 19.045,14.576 19.045,10.784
